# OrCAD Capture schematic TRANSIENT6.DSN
size A
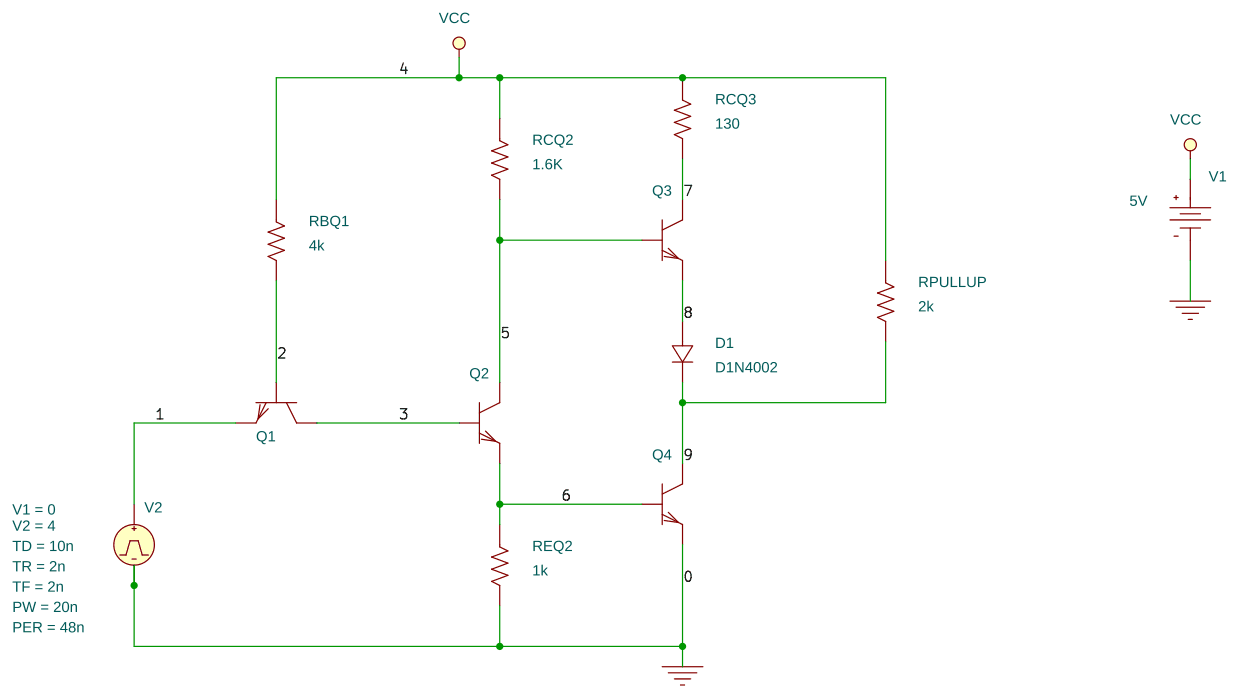
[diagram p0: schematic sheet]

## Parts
D1  D1N4002  [DO-41]
Q1  QbreakN
Q2  QbreakN
Q3  QbreakN
Q4  QbreakN
RBQ1  4k  [AX/RC05]
RCQ2  1.6K  [AX/RC05]
RCQ3  130  [AX/RC05]
REQ2  1k  [AX/RC05]
RPULLUP  2k  [AX/RC05]
V1  VDC
V2  VPULSE

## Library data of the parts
D1 = D1N4002
Q1-Q4 = QbreakN
RBQ1 RCQ2 RCQ3 REQ2 RPULLUP = R
V1 = VDC: DC: 5V
V2 = VPULSE: PER: 48n; PW: 20n; TD: 10n; TF: 2n; TR: 2n; V1: 0; V2: 4

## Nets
VCC: RBQ1.1 RCQ2.1 RCQ3.1 RPULLUP.1 V1.0(+)
0: Q4.2(e) REQ2.2 V1.1(-) V2.2(-)
1: Q1.2(e) V2.1(+)
2: Q1.0(b) RBQ1.2
3: Q1.1(c) Q2.0(b)
5: Q2.1(c) Q3.0(b) RCQ2.2
6: Q2.2(e) Q4.0(b) REQ2.1
7: Q3.1(c) RCQ3.2
8: D1.1 Q3.2(e)
9: D1.2 Q4.1(c) RPULLUP.2
